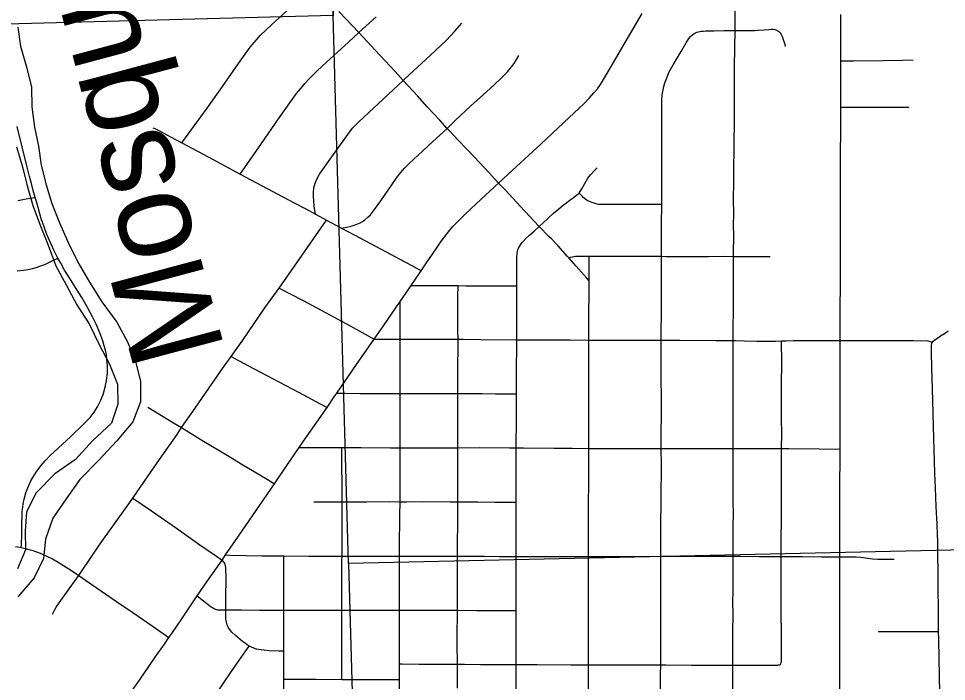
# Model space of a CAD drawing. Extents: x -6.4 to 34, y -4.2 to 22.
# Drawn here: x 4.508 to 5.453, y 14.536 to 15.21 of the extents above; entities that cross this region are included whole.
import ezdxf

# ---------------------------------------------------------------- set-up
doc = ezdxf.new("R2010")
doc.units = 0
for name, color, linetype in [('GM_X_City_Street', 7, 'Continuous'), ('GM_X_Corporation', 7, 'Continuous'), ('GM_X_County_Road', 7, 'Continuous'), ('GM_X_Major_River', 7, 'Continuous'), ('GM_X_Major_River_Text', 7, 'Continuous'), ('GM_X_State_Route', 7, 'Continuous')]:
    doc.layers.add(name, color=color, linetype=linetype)

msp = doc.modelspace()

# ---------------------------------------------------------------- linework, layer by layer
at = {"layer": 'GM_X_City_Street'}
for points in [[(4.67454, 15.08368), (4.70026, 15.11912), (4.71575, 15.14092), (4.73199, 15.16448), (4.74388, 15.18115), (4.75446, 15.1932), (4.76585, 15.20374), (4.79682, 15.23257), (4.80954, 15.2444), (4.8319, 15.26519), (4.83629, 15.26974), (4.83933, 15.27383), (4.84178, 15.27831), (4.84339, 15.28249), (4.84455, 15.28745), (4.84518, 15.29313), (4.8463, 15.33048), (4.84682, 15.35034), (4.84702, 15.36117)], [(5.23542, 14.50143), (5.23548, 14.54241), (5.23546, 14.5521), (5.23544, 14.56296), (5.23548, 14.57959), (5.23542, 14.58514), (5.23558, 14.60426), (5.23548, 14.61625), (5.2356, 14.62779), (5.23561, 14.64035), (5.23562, 14.65483), (5.23562, 14.66291), (5.23563, 14.67905), (5.23585, 14.69403), (5.23595, 14.70643), (5.23586, 14.71812), (5.2358, 14.74648), (5.23581, 14.77271), (5.23583, 14.79706), (5.23584, 14.80927), (5.23581, 14.8245), (5.23577, 14.83195), (5.23585, 14.84303), (5.2358, 14.86562), (5.23577, 14.86928), (5.23578, 14.88259), (5.23578, 14.89674), (5.23591, 14.91167), (5.23591, 14.91936), (5.23603, 14.92672), (5.23604, 14.93362), (5.23604, 14.94199), (5.23605, 14.95613), (5.23615, 14.96821), (5.23617, 14.97129), (5.23624, 14.98943), (5.23619, 15.00037), (5.23632, 15.01101), (5.23621, 15.02719), (5.23634, 15.04325), (5.23645, 15.05151), (5.23646, 15.06034), (5.2367, 15.07482), (5.23682, 15.08444), (5.23718, 15.10458), (5.23718, 15.12144), (5.23719, 15.13818), (5.23721, 15.16183), (5.23778, 15.19793), (5.23769, 15.20482), (5.23761, 15.22815)], [(5.08834, 14.52391), (5.08862, 14.54386), (5.0886, 14.55257), (5.08858, 14.5614), (5.08857, 14.58998), (5.08846, 14.60388), (5.08833, 14.61804), (5.08844, 14.63145), (5.08844, 14.66275), (5.08844, 14.67977), (5.08846, 14.7089), (5.08883, 14.74484), (5.08871, 14.76804), (5.08873, 14.77277), (5.08887, 14.79907), (5.08889, 14.8336), (5.08892, 14.87623), (5.08892, 14.883), (5.08894, 14.91103), (5.0891, 14.92908), (5.08923, 14.94057), (5.08927, 14.94317), (5.0868, 14.94597), (5.0837, 14.94948), (5.07589, 14.95811), (5.06849, 14.96664), (5.06714, 14.96819), (5.05717, 14.97919), (5.05088, 14.98591), (5.04824, 14.98836), (5.03832, 14.99868), (5.03279, 15.00444), (5.02907, 15.00852), (5.02327, 15.01465), (5.00352, 15.03594), (4.99696, 15.04278), (4.98733, 15.05309), (4.97256, 15.06901), (4.96485, 15.07706), (4.95573, 15.08634), (4.94742, 15.09546), (4.94447, 15.0985), (4.93695, 15.10683), (4.92418, 15.12042), (4.91434, 15.13158), (4.89995, 15.14727), (4.8917, 15.15626), (4.87139, 15.17813), (4.85473, 15.19599), (4.83446, 15.21757)], [(4.73393, 15.05197), (4.73613, 15.05515), (4.75553, 15.08322), (4.77294, 15.10823), (4.78622, 15.12683), (4.79126, 15.13399), (4.79554, 15.13918), (4.79951, 15.14422), (4.80394, 15.14894), (4.81234, 15.15702), (4.8218, 15.16586), (4.84409, 15.18629), (4.85473, 15.19599), (4.87218, 15.21191)], [(5.34349, 14.44136), (5.34352, 14.44413), (5.34396, 14.48137), (5.34404, 14.49549), (5.34415, 14.5246), (5.34442, 14.59744), (5.34442, 14.61435), (5.34445, 14.66239), (5.34447, 14.6757), (5.34445, 14.7372), (5.34452, 14.76081), (5.34456, 14.77197), (5.3448, 14.84685), (5.34477, 14.88248), (5.34476, 14.8893), (5.34514, 14.96513), (5.34516, 15.06116), (5.34519, 15.10752), (5.3452, 15.11989), (5.34521, 15.1367), (5.34528, 15.16717), (5.34538, 15.21444)], [(4.81037, 15.01122), (4.80983, 15.01483), (4.80915, 15.0194), (4.80882, 15.02478), (4.80865, 15.0289), (4.80854, 15.03308), (4.80895, 15.03789), (4.81016, 15.04255), (4.81225, 15.04757), (4.81471, 15.05176), (4.82896, 15.07197), (4.84517, 15.09475), (4.84864, 15.09905), (4.85457, 15.10527), (4.88962, 15.13772), (4.89995, 15.14727), (4.90593, 15.15282), (4.92725, 15.17262), (4.94389, 15.18841), (4.95208, 15.19696), (4.95934, 15.20553)], [(5.26103, 15.19827), (5.26718, 15.19885), (5.27193, 15.19924), (5.27447, 15.1994), (5.27648, 15.19935), (5.27844, 15.19898), (5.28077, 15.19799), (5.28175, 15.19726), (5.28347, 15.19566), (5.28457, 15.19407), (5.28551, 15.19187), (5.28665, 15.18892), (5.28787, 15.18512), (5.28872, 15.18181)], [(5.16175, 14.51522), (5.16185, 14.54252), (5.16195, 14.55243), (5.16201, 14.55933), (5.16203, 14.57892), (5.16212, 14.59606), (5.16205, 14.61216), (5.16214, 14.62446), (5.16208, 14.655), (5.16208, 14.66301), (5.16209, 14.67103), (5.16211, 14.69299), (5.16228, 14.72045), (5.16262, 14.75647), (5.16255, 14.77272), (5.16249, 14.7859), (5.16266, 14.80939), (5.16267, 14.82478), (5.16252, 14.84319), (5.16246, 14.86326), (5.16247, 14.8829), (5.16248, 14.8907), (5.16265, 14.9107), (5.16275, 14.93918), (5.16283, 14.96831), (5.16285, 14.97329), (5.1628, 15.0051), (5.16296, 15.01716), (5.16299, 15.0213), (5.16297, 15.03054), (5.16306, 15.0381), (5.16306, 15.04614), (5.16307, 15.05402), (5.16308, 15.07082), (5.16319, 15.08796), (5.16301, 15.09382), (5.16303, 15.10831), (5.16295, 15.11699), (5.16296, 15.12224), (5.16304, 15.12726), (5.16353, 15.13253), (5.16431, 15.13783), (5.16519, 15.14124), (5.16622, 15.14465), (5.16805, 15.15004), (5.16909, 15.15266), (5.17035, 15.15544), (5.17472, 15.16321), (5.18275, 15.17687), (5.18778, 15.18552), (5.19053, 15.18977), (5.19236, 15.192), (5.1949, 15.1943), (5.1968, 15.19548), (5.19858, 15.19628), (5.20045, 15.19683), (5.20298, 15.19731), (5.20521, 15.19754), (5.20746, 15.19768), (5.21163, 15.19781), (5.21593, 15.19785), (5.22647, 15.19796), (5.23778, 15.19793), (5.24005, 15.19793), (5.25795, 15.1982), (5.26103, 15.19827)], [(4.83708, 14.99694), (4.8422, 14.99788), (4.84574, 14.99856), (4.84894, 14.99947), (4.8526, 15.00085), (4.85592, 15.00244), (4.85832, 15.0037), (4.86072, 15.0053), (4.86381, 15.00816), (4.86645, 15.01056), (4.86965, 15.01467), (4.87698, 15.02462), (4.8882, 15.04097), (4.89415, 15.04954), (4.89896, 15.05548), (4.90159, 15.05845), (4.90537, 15.062), (4.91109, 15.0676), (4.91933, 15.07514), (4.92998, 15.08497), (4.94447, 15.0985), (4.95286, 15.10634), (4.96877, 15.12131), (4.98148, 15.13286), (4.992, 15.14246), (5.00059, 15.15057), (5.00608, 15.15617), (5.01287, 15.16437), (5.01754, 15.17258)], [(5.34528, 15.16717), (5.35812, 15.16717), (5.38806, 15.16762), (5.40811, 15.16792), (5.4188, 15.16808)], [(5.3452, 15.11989), (5.36262, 15.11997), (5.40457, 15.12017), (5.4146, 15.12021)], [(4.5108, 14.67184), (4.51113, 14.67504), (4.51131, 14.67796), (4.51156, 14.68219), (4.51158, 14.69692), (4.5118, 14.70352), (4.51202, 14.70872), (4.51245, 14.71284), (4.513, 14.71641), (4.51398, 14.72096), (4.51582, 14.72756), (4.51832, 14.73417), (4.52081, 14.73968), (4.52374, 14.74477), (4.52688, 14.74954), (4.53122, 14.75539), (4.53523, 14.76025), (4.54051, 14.76559), (4.56109, 14.78455), (4.57413, 14.79704), (4.581, 14.80433), (4.58525, 14.80979), (4.58861, 14.81511), (4.59176, 14.82128), (4.59432, 14.82771), (4.59652, 14.83493), (4.5979, 14.84171), (4.59865, 14.84922), (4.59875, 14.85676), (4.59828, 14.86304), (4.59774, 14.86802), (4.59665, 14.87257), (4.59546, 14.87708), (4.59396, 14.88221), (4.59104, 14.89023), (4.58725, 14.89933), (4.58357, 14.9068), (4.57818, 14.91673), (4.57269, 14.92639), (4.56805, 14.93383), (4.56194, 14.94352), (4.55514, 14.95429), (4.5512, 14.96128), (4.54837, 14.96631), (4.54766, 14.96758), (4.54431, 14.97441), (4.53977, 14.98437), (4.53716, 14.99062), (4.53382, 14.99939), (4.53177, 15.00549), (4.53002, 15.01151), (4.52818, 15.01803), (4.52615, 15.02521), (4.52528, 15.02817), (4.52323, 15.03518), (4.52133, 15.04228), (4.51939, 15.04952), (4.51702, 15.05904), (4.50671, 15.10053)], [(4.64497, 15.09917), (4.6469, 15.09822), (4.65095, 15.09617), (4.65534, 15.09392), (4.66287, 15.08991), (4.67454, 15.08368), (4.7063, 15.06662), (4.73393, 15.05197), (4.7447, 15.04626), (4.7887, 15.02276), (4.80053, 15.01652), (4.81037, 15.01122), (4.81498, 15.00874), (4.82182, 15.0051), (4.83708, 14.99694), (4.84999, 14.99006), (4.8773, 14.97543), (4.90154, 14.9628), (4.90912, 14.95856), (4.91808, 14.9535)], [(5.01471, 14.5216), (5.01486, 14.54828), (5.01487, 14.55267), (5.01489, 14.56136), (5.01484, 14.57364), (5.0149, 14.58498), (5.01483, 14.60787), (5.01495, 14.63532), (5.01495, 14.65653), (5.01497, 14.66273), (5.01482, 14.71797), (5.01472, 14.77327), (5.01522, 14.80465), (5.01523, 14.82818), (5.01523, 14.83261), (5.01528, 14.85035), (5.0154, 14.87965), (5.01541, 14.88334), (5.01543, 14.8954), (5.01543, 14.90614), (5.01544, 14.91704), (5.01545, 14.92334), (5.01545, 14.92994), (5.01545, 14.93821), (5.01545, 14.94831), (5.01545, 14.95695), (5.01546, 14.96274), (5.01559, 14.96693), (5.01587, 14.97124), (5.01628, 14.97394), (5.01722, 14.9765), (5.01917, 14.97983), (5.02055, 14.98183), (5.02178, 14.98336), (5.02501, 14.98674), (5.02823, 14.98965), (5.03337, 14.99418), (5.03832, 14.99868), (5.04708, 15.00674), (5.05295, 15.01209), (5.05837, 15.01672), (5.06254, 15.02022), (5.06625, 15.0231), (5.06975, 15.02557), (5.07295, 15.02783), (5.07501, 15.02938), (5.07881, 15.03249), (5.08157, 15.03702), (5.08467, 15.04245), (5.08783, 15.04768), (5.09077, 15.05159), (5.09414, 15.05515), (5.09721, 15.05815)], [(5.07881, 15.03249), (5.08231, 15.02899), (5.08432, 15.0273), (5.08601, 15.02617), (5.08787, 15.02511), (5.09091, 15.02375), (5.09404, 15.02254), (5.09704, 15.0217), (5.09877, 15.02147), (5.10077, 15.02134), (5.10787, 15.02121), (5.13095, 15.02131), (5.1603, 15.0213), (5.16299, 15.0213)], [(4.50764, 15.02506), (4.5159, 15.0266), (4.52463, 15.02807), (4.52528, 15.02817)], [(4.54285, 14.60395), (4.54483, 14.60806), (4.54668, 14.61128), (4.54956, 14.61562), (4.5608, 14.63124), (4.56956, 14.64347), (4.57237, 14.64739), (4.59147, 14.67551), (4.61873, 14.71399), (4.62455, 14.72217), (4.6364, 14.73925), (4.65188, 14.76154), (4.66959, 14.78706), (4.67427, 14.79386), (4.68799, 14.81381), (4.71594, 14.85406), (4.72464, 14.86635), (4.73644, 14.88304), (4.75904, 14.91574), (4.77355, 14.93594), (4.79706, 14.96955), (4.81934, 15.00152), (4.82182, 15.0051)], [(4.50684, 14.9534), (4.51317, 14.95417), (4.51788, 14.95494), (4.52228, 14.95587), (4.5263, 14.95694), (4.53085, 14.95841), (4.5349, 14.96005), (4.54057, 14.96268), (4.54762, 14.96596), (4.54837, 14.96631)], [(5.06849, 14.96664), (5.07026, 14.96722), (5.07215, 14.96786), (5.07362, 14.96814), (5.07526, 14.96837), (5.08079, 14.96847), (5.08925, 14.96835), (5.10122, 14.96842), (5.12599, 14.96853), (5.1401, 14.9683), (5.16003, 14.96836), (5.16283, 14.96831), (5.16738, 14.96823), (5.18575, 14.96801), (5.19755, 14.96805), (5.21058, 14.96811), (5.22697, 14.96824), (5.23615, 14.96821)], [(5.08927, 14.94317), (5.08925, 14.96067), (5.08925, 14.9658), (5.08925, 14.96835)], [(5.23615, 14.96821), (5.24303, 14.96819), (5.25527, 14.96816), (5.26376, 14.96808), (5.27356, 14.96799)], [(4.77355, 14.93594), (4.79797, 14.92341), (4.8207, 14.91106), (4.84581, 14.89733), (4.86425, 14.88729), (4.87019, 14.88406)], [(4.90789, 14.9387), (4.91525, 14.9387), (4.92573, 14.93869), (4.9363, 14.93859), (4.94781, 14.93847), (4.95572, 14.93842), (4.96362, 14.93836), (4.97934, 14.93835), (5.0119, 14.93822), (5.01545, 14.93821)], [(4.95505, 14.52872), (4.95507, 14.54056), (4.95503, 14.55301), (4.95502, 14.55536), (4.95492, 14.57197), (4.95492, 14.58511), (4.95505, 14.60264), (4.95509, 14.60794), (4.95512, 14.61558), (4.95505, 14.64311), (4.95506, 14.65199), (4.95517, 14.66296), (4.95537, 14.70972), (4.95537, 14.71828), (4.95538, 14.73104), (4.9555, 14.75299), (4.95551, 14.76625), (4.95548, 14.77347), (4.95547, 14.78423), (4.9556, 14.79863), (4.95535, 14.82331), (4.95542, 14.82868), (4.95545, 14.83122), (4.95545, 14.83877), (4.95546, 14.8465), (4.95555, 14.85564), (4.95574, 14.87572), (4.95566, 14.88378), (4.95558, 14.89188), (4.95542, 14.91489), (4.9556, 14.92945), (4.9557, 14.93655), (4.95572, 14.93842)], [(4.89616, 14.50512), (4.89593, 14.5376), (4.89591, 14.55066), (4.89592, 14.55352), (4.89598, 14.57667), (4.89604, 14.59865), (4.8961, 14.60804), (4.89616, 14.64125), (4.89619, 14.66299), (4.89621, 14.67189), (4.89655, 14.70461), (4.89668, 14.71853), (4.89663, 14.74393), (4.89664, 14.76834), (4.89666, 14.77336), (4.89679, 14.80301), (4.89685, 14.82429), (4.89685, 14.82852), (4.89684, 14.84168), (4.89671, 14.87627), (4.89668, 14.8839), (4.89661, 14.90337), (4.89662, 14.91338), (4.89663, 14.9222)], [(5.43859, 14.88096), (5.43932, 14.88187), (5.44092, 14.88325), (5.44264, 14.88443), (5.44696, 14.88719), (5.45073, 14.88976), (5.45451, 14.89233)], [(4.87019, 14.88406), (4.87702, 14.88402), (4.89668, 14.8839), (4.92907, 14.88389), (4.95566, 14.88378), (4.961, 14.88376), (4.97892, 14.88365), (5.01436, 14.88334), (5.01541, 14.88334), (5.03117, 14.88331), (5.05168, 14.8832), (5.0699, 14.88308), (5.08892, 14.883), (5.09482, 14.88297), (5.11694, 14.88285), (5.15007, 14.88283), (5.16247, 14.8829), (5.16649, 14.88292), (5.1815, 14.88291), (5.21803, 14.88269), (5.23578, 14.88259), (5.23855, 14.88257), (5.24676, 14.88226), (5.25997, 14.88195), (5.27869, 14.88174), (5.28488, 14.88208), (5.28949, 14.88233), (5.2969, 14.88253), (5.31542, 14.88242), (5.33444, 14.88241), (5.34477, 14.88248), (5.34685, 14.88249), (5.36036, 14.88249), (5.37988, 14.88248), (5.3984, 14.88246), (5.41921, 14.88244), (5.43373, 14.88224), (5.43859, 14.88096)], [(5.28391, 14.55296), (5.28433, 14.5535), (5.28474, 14.55477), (5.28482, 14.55572), (5.28482, 14.58156), (5.28473, 14.60788), (5.28452, 14.63921), (5.28464, 14.66277), (5.28463, 14.6701), (5.28482, 14.71003), (5.28501, 14.73619), (5.28503, 14.76531), (5.28506, 14.77267), (5.28513, 14.78835), (5.28506, 14.80261), (5.28499, 14.833), (5.2851, 14.86473), (5.28502, 14.87688), (5.28488, 14.88208)], [(5.44603, 14.52413), (5.44533, 14.55891), (5.44504, 14.57825), (5.44492, 14.5865), (5.44482, 14.59328), (5.44438, 14.64616), (5.44418, 14.66474), (5.44402, 14.6791), (5.44386, 14.68417), (5.44345, 14.69624), (5.44319, 14.70143), (5.44253, 14.71346), (5.442, 14.72302), (5.44162, 14.73252), (5.44113, 14.74742), (5.43969, 14.79515), (5.43893, 14.82158), (5.43822, 14.84409), (5.43792, 14.85423), (5.43757, 14.87165), (5.43757, 14.87542), (5.43763, 14.87785), (5.43785, 14.87929), (5.43811, 14.88005), (5.43859, 14.88096)], [(4.72464, 14.86635), (4.73212, 14.86232), (4.748, 14.85378), (4.7673, 14.84369), (4.79328, 14.83014), (4.81535, 14.81822), (4.82225, 14.81453)], [(4.83235, 14.82911), (4.83528, 14.82906), (4.84077, 14.82894), (4.85584, 14.82862), (4.88248, 14.82849), (4.8925, 14.82851), (4.89685, 14.82852), (4.90318, 14.82853), (4.9229, 14.82861), (4.94995, 14.82867), (4.95542, 14.82868), (4.96042, 14.82869), (4.98023, 14.82854), (4.99371, 14.82843), (5.0082, 14.82827), (5.01307, 14.82821), (5.01523, 14.82818)], [(4.64, 14.81458), (4.66601, 14.7989), (4.67427, 14.79386), (4.6966, 14.78025), (4.72065, 14.7658), (4.73495, 14.7572), (4.76134, 14.74135), (4.76884, 14.73684)], [(4.79401, 14.77364), (4.80035, 14.77363), (4.81889, 14.77359), (4.83742, 14.77355), (4.85705, 14.77351), (4.88698, 14.77339), (4.89666, 14.77336), (4.90115, 14.77334), (4.95096, 14.77347), (4.95548, 14.77347), (4.97785, 14.77351), (5.00805, 14.77331), (5.01472, 14.77327), (5.02228, 14.77323), (5.05353, 14.77297), (5.0717, 14.77287), (5.08873, 14.77277), (5.09935, 14.7727), (5.11823, 14.77275), (5.13571, 14.77279), (5.16255, 14.77272), (5.16749, 14.7727), (5.17794, 14.77274), (5.19781, 14.77281), (5.22836, 14.7727), (5.23581, 14.77271), (5.25165, 14.77271), (5.27933, 14.77275), (5.28506, 14.77267), (5.29247, 14.77257), (5.32315, 14.77215), (5.34456, 14.77197)], [(4.83742, 14.5377), (4.83743, 14.54298), (4.83736, 14.56127), (4.83729, 14.57963), (4.83729, 14.59455), (4.83731, 14.60825), (4.83736, 14.61639), (4.8375, 14.63575), (4.83751, 14.6587), (4.83752, 14.66301), (4.83753, 14.68757), (4.83766, 14.70447), (4.83762, 14.71827), (4.83742, 14.77355)], [(4.62455, 14.72217), (4.64369, 14.70909), (4.66893, 14.6915), (4.69285, 14.67458), (4.70967, 14.6631), (4.71536, 14.65916)], [(4.809, 14.71842), (4.82552, 14.71832), (4.83762, 14.71827), (4.84274, 14.71828), (4.86278, 14.7184), (4.88623, 14.71854), (4.89668, 14.71853), (4.90332, 14.71853), (4.91977, 14.71858), (4.94753, 14.71832), (4.95537, 14.71828), (4.97578, 14.71821), (4.99318, 14.71816), (5.00847, 14.71803), (5.01482, 14.71797)], [(4.71895, 14.66437), (4.72321, 14.66414), (4.75576, 14.66347), (4.76728, 14.66338), (4.77818, 14.6633), (4.8036, 14.66321), (4.83752, 14.66301), (4.8578, 14.66303), (4.89619, 14.66299), (4.91318, 14.66291), (4.93164, 14.6629), (4.94301, 14.6629), (4.95517, 14.66296), (4.96687, 14.66303), (4.98274, 14.66294), (4.99773, 14.66286), (5.01497, 14.66273), (5.01788, 14.66273), (5.01972, 14.66268), (5.02896, 14.66268), (5.03639, 14.66268), (5.07341, 14.66273), (5.08375, 14.66272), (5.08844, 14.66275), (5.09801, 14.66279), (5.124, 14.66285), (5.16208, 14.66301), (5.1683, 14.66303), (5.20064, 14.66303), (5.21497, 14.663), (5.23077, 14.66292), (5.23562, 14.66291), (5.2431, 14.66291), (5.26252, 14.66275), (5.28328, 14.66277), (5.28464, 14.66277), (5.30623, 14.66269), (5.3255, 14.66249), (5.34445, 14.66239), (5.3535, 14.66252), (5.36108, 14.66237), (5.36564, 14.66208), (5.37232, 14.66119), (5.37741, 14.66045), (5.38273, 14.66008), (5.38745, 14.65993), (5.39979, 14.65985)], [(4.77831, 14.44253), (4.77831, 14.4476), (4.77842, 14.48263), (4.77831, 14.50629), (4.77832, 14.53785), (4.77833, 14.55299), (4.77829, 14.56638), (4.77826, 14.57882), (4.77817, 14.60823), (4.77814, 14.61525), (4.77816, 14.63943), (4.77818, 14.65867), (4.77818, 14.6633)], [(4.77829, 14.56638), (4.77324, 14.56648), (4.76346, 14.56682), (4.75827, 14.56724), (4.75515, 14.56757), (4.75268, 14.56798), (4.75038, 14.56855), (4.74767, 14.56938), (4.74553, 14.57029), (4.74294, 14.57163), (4.74109, 14.57275), (4.73912, 14.57416), (4.73615, 14.5763), (4.72917, 14.58221), (4.72553, 14.58572), (4.72303, 14.58865), (4.72225, 14.58977), (4.72162, 14.59085), (4.72096, 14.59212), (4.72057, 14.59325), (4.72016, 14.59446), (4.71977, 14.59601), (4.71961, 14.59748), (4.71941, 14.59903), (4.71936, 14.6026), (4.71941, 14.60831), (4.71942, 14.62041), (4.71949, 14.64097), (4.71942, 14.6501), (4.71926, 14.65166), (4.71902, 14.65314), (4.7187, 14.65436), (4.7183, 14.65553), (4.71772, 14.65651), (4.71704, 14.65744), (4.71636, 14.65824), (4.71536, 14.65916)], [(4.69013, 14.62253), (4.69516, 14.61853), (4.70447, 14.61161), (4.70565, 14.61075), (4.70661, 14.61011), (4.70766, 14.60952), (4.70865, 14.60907), (4.70955, 14.60874), (4.71068, 14.60849), (4.71181, 14.60836), (4.7133, 14.60831), (4.71941, 14.60831), (4.73506, 14.60829), (4.75366, 14.60827), (4.77817, 14.60823), (4.7984, 14.60819), (4.81519, 14.60821), (4.83731, 14.60825), (4.85142, 14.60823), (4.87457, 14.60813), (4.8961, 14.60804), (4.91106, 14.60804), (4.93551, 14.60797), (4.95509, 14.60794), (4.9745, 14.60792), (5.00857, 14.60788), (5.01483, 14.60787)], [(5.38332, 14.58645), (5.39984, 14.58647), (5.43201, 14.58649), (5.44399, 14.5865), (5.44492, 14.5865)], [(4.68859, 14.49372), (4.69215, 14.4986), (4.70637, 14.51827), (4.71808, 14.53586), (4.7277, 14.54959), (4.73952, 14.56667), (4.74294, 14.57163)], [(4.89592, 14.55352), (4.89887, 14.55348), (4.91619, 14.55329), (4.93592, 14.55311), (4.95503, 14.55301), (4.96216, 14.55298), (4.97849, 14.55283), (4.99839, 14.55282), (5.00662, 14.55268), (5.01487, 14.55267), (5.01966, 14.55267), (5.03612, 14.55266), (5.07058, 14.5526), (5.0816, 14.55252), (5.0886, 14.55257), (5.09609, 14.55262), (5.10982, 14.55261), (5.13781, 14.5524), (5.16195, 14.55243), (5.16732, 14.55243), (5.19326, 14.55214), (5.21714, 14.55212), (5.23401, 14.55211), (5.23546, 14.5521), (5.24882, 14.55199), (5.25563, 14.55202), (5.2655, 14.55212), (5.28099, 14.55227), (5.28198, 14.5523), (5.28278, 14.55243), (5.28391, 14.55296)], [(4.77832, 14.53785), (4.78438, 14.53786), (4.81078, 14.53778), (4.83742, 14.5377), (4.85716, 14.53765), (4.8777, 14.5376), (4.89593, 14.5376)]]:
    msp.add_lwpolyline(points, dxfattribs=at)
at = {"layer": 'GM_X_Corporation'}
for points in [[(4.92466, 15.86229), (5.93632, 15.88385), (5.96639, 14.68043), (5.96322, 14.68037), (4.84426, 14.65545), (4.82849, 15.2133), (4.81021, 15.86007)], [(3.94651, 15.8436), (4.81021, 15.86007), (4.82849, 15.2133), (4.41851, 15.20239), (4.0324, 15.19212), (3.70187, 15.18694), (3.30855, 15.18118), (3.23887, 15.18016), (3.22314, 15.8313)], [(4.85874, 14.1), (5.97939, 14.1), (5.96639, 14.68043), (5.96322, 14.68037), (4.84426, 14.65545), (4.84993, 14.45297)]]:
    msp.add_lwpolyline(points, close=True, dxfattribs=at)
at = {"layer": 'GM_X_County_Road'}
msp.add_lwpolyline([(4.50505, 14.67279), (4.5108, 14.67184), (4.51372, 14.67127), (4.51749, 14.67033), (4.52164, 14.66916), (4.52638, 14.66746), (4.53189, 14.66534), (4.53711, 14.66293), (4.54269, 14.66024), (4.54849, 14.65699), (4.55407, 14.65373), (4.56205, 14.64857), (4.56864, 14.6441), (4.56956, 14.64347), (4.57653, 14.63874), (4.60808, 14.61688), (4.62449, 14.60559), (4.64412, 14.59208), (4.65769, 14.58278), (4.66128, 14.58019)], dxfattribs=at)
at = {"layer": 'GM_X_Major_River'}
for points in [[(4.5075, 15.20143), (4.51018, 15.18213), (4.51671, 15.15988), (4.52129, 15.14025), (4.52171, 15.12052), (4.52442, 15.09971), (4.52862, 15.08044), (4.5313, 15.06115), (4.53627, 15.04114), (4.54198, 15.02191), (4.54997, 15.00235), (4.55912, 14.98167), (4.56862, 14.96214), (4.58042, 14.9419), (4.59296, 14.92206), (4.60818, 14.90113), (4.6192, 14.88125), (4.6272, 14.86131), (4.63255, 14.84131), (4.63224, 14.82006), (4.62472, 14.79978), (4.60846, 14.78046), (4.58956, 14.76033), (4.57065, 14.74095), (4.55667, 14.7213), (4.54307, 14.70165), (4.53557, 14.68024), (4.5337, 14.66085), (4.52427, 14.64091), (4.50764, 14.62159)], [(4.50628, 15.07959), (4.5124, 15.05923), (4.51697, 15.03997), (4.5227, 15.01998), (4.53032, 15.00003), (4.53832, 14.97971), (4.54635, 14.95863), (4.55661, 14.93911), (4.56764, 14.91886), (4.58018, 14.89939), (4.59047, 14.87836), (4.60074, 14.85847), (4.60913, 14.83816), (4.60918, 14.81767), (4.60277, 14.79856), (4.58346, 14.78031), (4.56605, 14.76134), (4.54514, 14.74685), (4.52623, 14.72748), (4.51641, 14.7083), (4.51493, 14.68853), (4.51533, 14.66956), (4.50703, 14.65003)]]:
    msp.add_lwpolyline(points, dxfattribs=at)
at = {"layer": 'GM_X_State_Route'}
for points in [[(4.67436, 14.59943), (4.67774, 14.60442), (4.69013, 14.62253), (4.70003, 14.63695), (4.71536, 14.65916), (4.71781, 14.66272), (4.71895, 14.66437), (4.72914, 14.67916), (4.7538, 14.71495), (4.76884, 14.73684), (4.78084, 14.75429), (4.79401, 14.77364), (4.80151, 14.78467), (4.82225, 14.81453), (4.83028, 14.8261), (4.83235, 14.82911), (4.85239, 14.8582), (4.87019, 14.88406), (4.87968, 14.89764), (4.89663, 14.9222), (4.90274, 14.9312), (4.90789, 14.9387), (4.91808, 14.9535), (4.92285, 14.96044), (4.93397, 14.97705), (4.93882, 14.98395), (4.9445, 14.99151), (4.94722, 14.99497), (4.95051, 14.99875), (4.95364, 15.00203), (4.9567, 15.00516), (4.96213, 15.01058), (4.96859, 15.01662), (4.97872, 15.02597), (4.99289, 15.03903), (4.99696, 15.04278), (5.01125, 15.05595), (5.03988, 15.08225), (5.06325, 15.10435), (5.08413, 15.12384), (5.08961, 15.12968), (5.09399, 15.13452), (5.09745, 15.13875), (5.10058, 15.1431), (5.10684, 15.15313), (5.12586, 15.18577), (5.14298, 15.21553)], [(4.60715, 14.50197), (4.61446, 14.51254), (4.62634, 14.52971), (4.62902, 14.53354), (4.63586, 14.54342), (4.64743, 14.56013), (4.65671, 14.57352), (4.66128, 14.58019), (4.66422, 14.58445), (4.67436, 14.59943)]]:
    msp.add_lwpolyline(points, dxfattribs=at)

# ---------------------------------------------------------------- texts
at = {"layer": 'GM_X_Major_River_Text'}
msp.add_text('Mosquito', height=0.094733, rotation=104.97612, dxfattribs=at).set_placement((4.71855, 14.87358))

doc.saveas('drawing.dxf')
